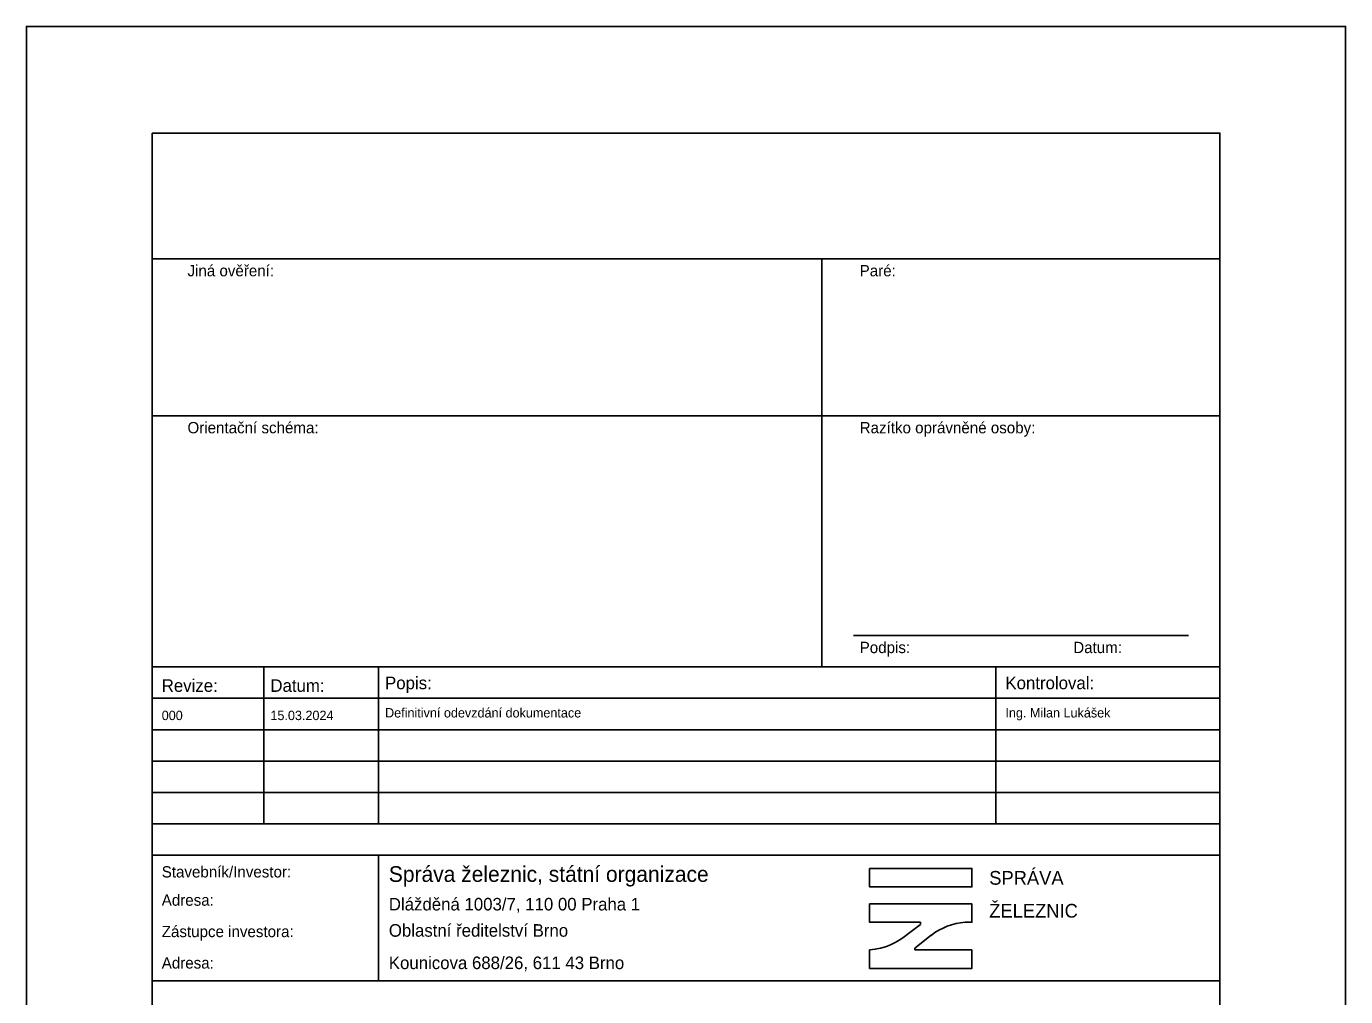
# Model space of a CAD drawing. Extents: x -122.1 to -101.1, y 467.3 to 497.
# Drawn here: x -122.06 to -101.06, y 481.6 to 497.05 of the extents above; entities that cross this region are included whole.
import ezdxf

# ---------------------------------------------------------------- set-up
doc = ezdxf.new("R2010")
doc.units = 0
for name, color, linetype in [('Default', 7, 'Continuous'), ('Rozpiska_Logo', 7, 'Continuous'), ('Rozpiska_pola_3', 7, 'Continuous'), ('Rozpiska_pole_1', 7, 'Continuous'), ('Rozpiska_pole_2', 7, 'Continuous'), ('Rozpiska_pole_4', 7, 'Continuous'), ('Rozpiska_pole_5', 7, 'Continuous'), ('Rozpiska_pole_6', 7, 'Continuous')]:
    doc.layers.add(name, color=color, linetype=linetype)

msp = doc.modelspace()

# ---------------------------------------------------------------- linework, layer by layer
at = {"layer": 'Default'}
for p, q in [((-101.063, 497.049), (-122.063, 497.049)), ((-122.063, 497.049), (-122.063, 467.349)), ((-101.063, 467.349), (-101.063, 497.049)), ((-109.398, 486.849), (-109.398, 493.349))]:
    msp.add_line(p, q, dxfattribs=at)
msp.add_lwpolyline([(-122.063, 467.349), (-101.063, 467.349), (-101.063, 497.049), (-122.063, 497.049)], close=True, dxfattribs=at)
at = {"layer": 'Rozpiska_Logo'}
for p, q in [((-108.023, 482.602), (-107.829, 482.748)), ((-107.829, 482.748), (-107.829, 482.783)), ((-107.66, 482.575), (-107.921, 482.373)), ((-107.921, 482.373), (-107.921, 482.342))]:
    msp.add_line(p, q, dxfattribs=at)
msp.add_lwpolyline([(-108.641, 483.64), (-107.011, 483.64), (-107.011, 483.347), (-108.641, 483.347)], close=True, dxfattribs=at)
for points in [[(-107.829, 482.783), (-108.641, 482.783), (-108.641, 483.076), (-107.011, 483.076), (-107.011, 482.783), (-107.118, 482.783)], [(-107.921, 482.342), (-107.011, 482.342), (-107.011, 482.049), (-108.641, 482.049), (-108.641, 482.342), (-108.634, 482.342)]]:
    msp.add_lwpolyline(points, dxfattribs=at)
for centre, radius, start, end in [((-108.719, 483.391), 1.052, 274.6014, 311.4254), ((-107.044, 481.781), 1.004, 94.2142, 127.7808)]:
    msp.add_arc(centre, radius, start, end, dxfattribs=at)
at = {"layer": 'Rozpiska_pola_3'}
msp.add_line((-108.898, 487.349), (-103.563, 487.349), dxfattribs=at)
at = {"layer": 'Rozpiska_pole_1'}
msp.add_lwpolyline([(-120.063, 495.349), (-103.063, 495.349), (-103.063, 468.849), (-120.063, 468.849)], close=True, dxfattribs=at)
at = {"layer": 'Rozpiska_pole_2'}
for points in [[(-120.063, 493.349), (-109.398, 493.349), (-109.398, 490.849), (-120.063, 490.849)], [(-109.398, 493.349), (-103.063, 493.349), (-103.063, 490.849), (-109.398, 490.849)], [(-120.063, 490.849), (-109.398, 490.849), (-109.398, 486.849), (-120.063, 486.849)], [(-103.063, 490.849), (-109.398, 490.849), (-109.398, 486.849), (-103.063, 486.849)]]:
    msp.add_lwpolyline(points, close=True, dxfattribs=at)
at = {"layer": 'Rozpiska_pole_4'}
for p, q in [((-118.285, 484.349), (-118.285, 486.849)), ((-116.458, 484.349), (-116.458, 486.849)), ((-106.633, 484.349), (-106.633, 486.849)), ((-120.063, 486.349), (-103.063, 486.349)), ((-120.063, 485.849), (-103.063, 485.849)), ((-120.063, 485.349), (-103.063, 485.349)), ((-120.063, 484.849), (-103.063, 484.849))]:
    msp.add_line(p, q, dxfattribs=at)
msp.add_lwpolyline([(-120.063, 486.849), (-103.063, 486.849), (-103.063, 484.349), (-120.063, 484.349)], close=True, dxfattribs=at)
at = {"layer": 'Rozpiska_pole_5'}
msp.add_line((-116.458, 481.849), (-116.458, 483.849), dxfattribs=at)
msp.add_lwpolyline([(-120.063, 483.849), (-103.063, 483.849), (-103.063, 481.849), (-120.063, 481.849)], close=True, dxfattribs=at)

# ---------------------------------------------------------------- texts
at = {"layer": 'Rozpiska_pola_3'}
for s, p in [('Paré:', (-108.798, 493.069)), ('Razítko oprávněné osoby:', (-108.798, 490.569)), ('Podpis:', (-108.798, 487.069)), ('Datum:', (-105.398, 487.069))]:
    msp.add_text(s, height=0.18, dxfattribs=at).set_placement(p)
at = {"layer": 'Rozpiska_pole_2'}
for s, p in [('Jiná ověření:', (-119.498, 493.069)), ('Orientační schéma:', (-119.498, 490.569))]:
    msp.add_text(s, height=0.18, dxfattribs=at).set_placement(p)
at = {"layer": 'Rozpiska_pole_4'}
for s, height, p in [('Revize:', 0.2, (-119.908, 486.452)), ('Datum:', 0.2, (-118.178, 486.452)), ('Popis:', 0.2, (-116.353, 486.494)), ('Kontroloval:', 0.2, (-106.478, 486.494)), ('000', 0.15, (-119.908, 486.002)), ('15.03.2024', 0.15, (-118.178, 486.002)), ('Definitivní odevzdání dokumentace', 0.15, (-116.353, 486.044)), ('Ing. Milan Lukášek', 0.15, (-106.478, 486.044))]:
    msp.add_text(s, height=height, dxfattribs=at).set_placement(p)
at = {"layer": 'Rozpiska_pole_5'}
for s, height, p in [('Stavebník/Investor:', 0.18, (-119.908, 483.496)), ('Správa železnic, státní organizace', 0.25, (-116.293, 483.426)), ('Adresa:', 0.18, (-119.908, 483.046)), ('Zástupce investora:', 0.18, (-119.908, 482.546)), ('Adresa:', 0.18, (-119.908, 482.046))]:
    msp.add_text(s, height=height, dxfattribs=at).set_placement(p)
at = {"layer": 'Rozpiska_pole_6'}
for s, height, p in [('SPRÁVA', 0.2183, (-106.736, 483.381)), ('Dlážděná 1003/7, 110 00 Praha 1', 0.2, (-116.293, 482.971)), ('ŽELEZNIC', 0.2183, (-106.736, 482.857)), ('Oblastní ředitelství Brno', 0.2, (-116.293, 482.553)), ('Kounicova 688/26, 611 43 Brno', 0.2, (-116.293, 482.037))]:
    msp.add_text(s, height=height, dxfattribs=at).set_placement(p)

doc.saveas('drawing.dxf')
